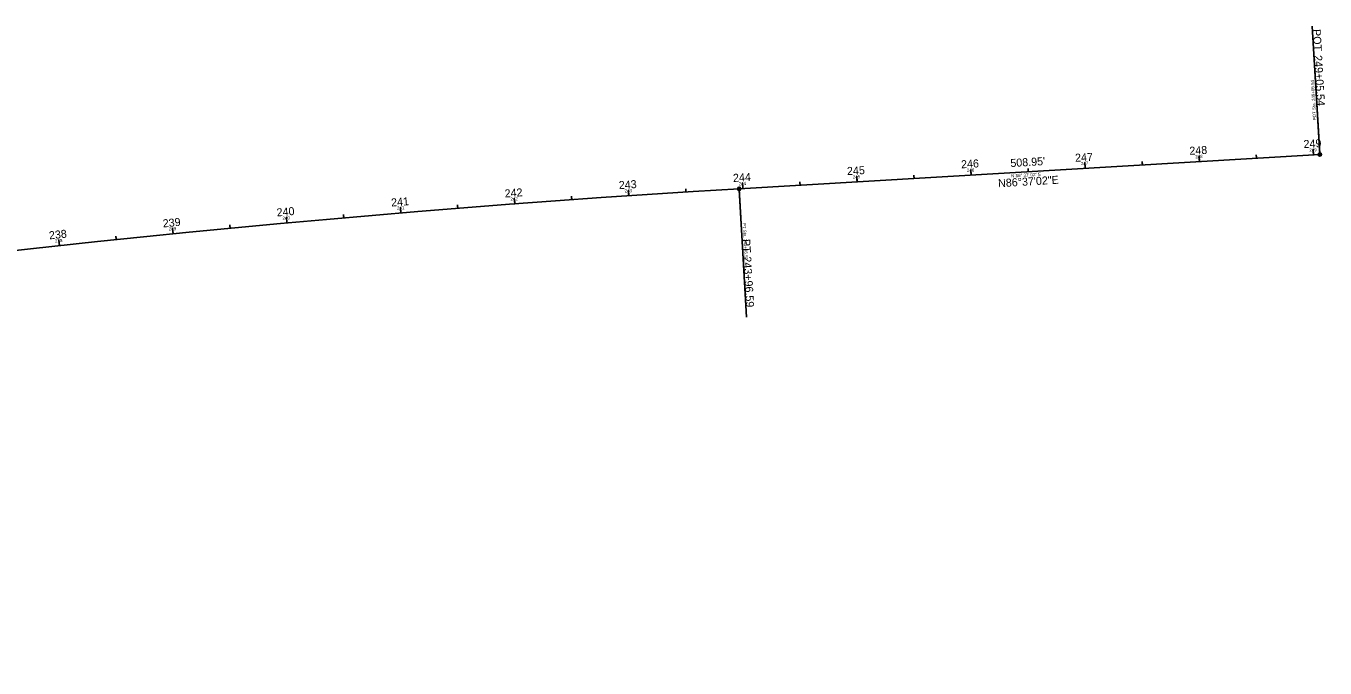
# Model space of a CAD drawing. Extents: x 2129507 to 2138391, y 657622 to 659877.
# Drawn here: x 2137254 to 2138391, y 659316 to 659877 of the extents above; entities that cross this region are included whole.
import ezdxf

# ---------------------------------------------------------------- set-up
doc = ezdxf.new("R2010")
doc.units = 0
for name, color, linetype in [('Default', 7, 'Continuous'), ('GE_X_Alignment_1000_Stations', 7, 'Continuous'), ('GE_X_Alignment_100_Stations', 7, 'Continuous'), ('GE_X_Alignment_500_Stations', 7, 'Continuous'), ('GE_X_CL_20', 7, 'Continuous'), ('MT_P_CL_20', 7, 'Continuous')]:
    doc.layers.add(name, color=color, linetype=linetype)

msp = doc.modelspace()

# ---------------------------------------------------------------- linework, layer by layer
at = {"layer": 'Default'}
for centre in [(2138380.7, 659764.2), (2138386.2, 659764.5), (2138386.2, 659764.5), (2138386.2, 659764.5), (2138181, 659752.4), (2138280.9, 659758.3), (2137981.4, 659740.6), (2137981.4, 659740.6), (2138081.2, 659746.5), (2138132.2, 659749.5), (2138132.2, 659749.5), (2138132.2, 659749.5), (2138132.2, 659749.5), (2138132.2, 659749.5), (2138132.2, 659749.5), (2137878.2, 659734.5), (2137878.2, 659734.5), (2137878.2, 659734.5), (2137881.6, 659734.7), (2137682, 659721.3), (2137781.8, 659728.4), (2137582.3, 659713.4), (2137383.2, 659695.2), (2137482.7, 659704.7), (2137482.7, 659704.7), (2137482.7, 659704.7), (2137283.7, 659684.8)]:
    msp.add_circle(centre, 0.0000833, dxfattribs=at)
at = {"layer": 'GE_X_Alignment_1000_Stations'}
for p, q in [((2138386.2, 659764.5), (2138379.6, 659876.8)), ((2137981.4, 659740.6), (2137981.2, 659743.6)), ((2137878.2, 659734.5), (2137884.8, 659622.2)), ((2137482.7, 659704.7), (2137482.3, 659709.7))]:
    msp.add_line(p, q, dxfattribs=at)
for centre in [(2138386.2, 659764.5), (2137878.2, 659734.5)]:
    msp.add_circle(centre, 1.5, dxfattribs=at)
at = {"layer": 'GE_X_Alignment_100_Stations'}
for p, q in [((2138386.2, 659764.5), (2138379.6, 659876.8)), ((2138280.9, 659758.3), (2138280.6, 659763.3)), ((2138330.8, 659761.2), (2138330.6, 659764.2)), ((2138380.7, 659764.2), (2138380.4, 659769.2)), ((2138081.2, 659746.5), (2138080.9, 659751.5)), ((2138131.1, 659749.4), (2138131, 659752.4)), ((2138181, 659752.4), (2138180.7, 659757.4)), ((2138231, 659755.3), (2138230.8, 659758.3)), ((2137931.5, 659737.6), (2137931.3, 659740.6)), ((2137981.4, 659740.6), (2137981.1, 659745.6)), ((2138031.3, 659743.5), (2138031.1, 659746.5)), ((2137781.8, 659728.4), (2137781.4, 659733.4)), ((2137831.7, 659731.7), (2137831.5, 659734.6)), ((2137878.2, 659734.5), (2137884.8, 659622.2)), ((2137881.6, 659734.7), (2137881.3, 659739.7)), ((2137582.3, 659713.4), (2137581.9, 659718.4)), ((2137632.2, 659717.5), (2137631.9, 659720.5)), ((2137682, 659721.3), (2137681.6, 659726.3)), ((2137731.9, 659725), (2137731.7, 659728)), ((2137482.7, 659704.7), (2137482.3, 659709.7)), ((2137532.5, 659709.2), (2137532.2, 659712.1)), ((2137383.2, 659695.2), (2137382.7, 659700.1)), ((2137432.9, 659700), (2137432.6, 659703)), ((2137283.7, 659684.8), (2137283.2, 659689.8)), ((2137333.4, 659690.1), (2137333.1, 659693.1))]:
    msp.add_line(p, q, dxfattribs=at)
for centre in [(2138386.2, 659764.5), (2137878.2, 659734.5)]:
    msp.add_circle(centre, 1.5, dxfattribs=at)
at = {"layer": 'GE_X_Alignment_500_Stations'}
for p, q in [((2138386.2, 659764.5), (2138379.6, 659876.8)), ((2138380.7, 659764.2), (2138380.5, 659767.2)), ((2138181, 659752.4), (2138180.9, 659755.4)), ((2138280.9, 659758.3), (2138280.7, 659761.3)), ((2137981.4, 659740.6), (2137981.1, 659745.6)), ((2138081.2, 659746.5), (2138081, 659749.5)), ((2137781.8, 659728.4), (2137781.6, 659731.4)), ((2137878.2, 659734.5), (2137884.8, 659622.2)), ((2137881.6, 659734.7), (2137881.4, 659737.7)), ((2137682, 659721.3), (2137681.8, 659724.3)), ((2137482.7, 659704.7), (2137482.3, 659709.7)), ((2137582.3, 659713.4), (2137582.1, 659716.4)), ((2137383.2, 659695.2), (2137382.9, 659698.2)), ((2137283.7, 659684.8), (2137283.4, 659687.8))]:
    msp.add_line(p, q, dxfattribs=at)
for centre in [(2138386.2, 659764.5), (2137878.2, 659734.5)]:
    msp.add_circle(centre, 1.5, dxfattribs=at)
at = {"layer": 'GE_X_CL_20'}
for p, q in [((2138386.2, 659765.5), (2138381.9, 659838.4)), ((2137878.2, 659734.5), (2138386.2, 659764.5)), ((2138330.8, 659761.2), (2138330.7, 659763.2)), ((2138380.7, 659764.2), (2138380.6, 659766.2)), ((2138131.1, 659749.4), (2138131, 659751.4)), ((2138181, 659752.4), (2138180.9, 659754.4)), ((2138231, 659755.3), (2138230.8, 659757.3)), ((2138280.9, 659758.3), (2138280.7, 659760.3)), ((2137981.4, 659740.6), (2137981.3, 659742.6)), ((2138031.3, 659743.5), (2138031.2, 659745.5)), ((2138081.2, 659746.5), (2138081.1, 659748.5)), ((2137781.8, 659728.4), (2137781.6, 659730.4)), ((2137831.7, 659731.7), (2137831.5, 659733.6)), ((2137878.2, 659733.5), (2137882.3, 659663.8)), ((2137881.6, 659734.7), (2137881.4, 659736.7)), ((2137931.5, 659737.6), (2137931.4, 659739.6)), ((2137632.2, 659717.5), (2137632, 659719.5)), ((2137682, 659721.3), (2137681.9, 659723.3)), ((2137731.9, 659725), (2137731.7, 659727)), ((2137482.7, 659704.7), (2137482.5, 659706.7)), ((2137532.5, 659709.2), (2137532.3, 659711.2)), ((2137582.3, 659713.4), (2137582.2, 659715.4)), ((2137383.2, 659695.2), (2137383, 659697.2)), ((2137432.9, 659700), (2137432.7, 659702)), ((2137283.7, 659684.8), (2137283.5, 659686.8)), ((2137333.4, 659690.1), (2137333.2, 659692.1))]:
    msp.add_line(p, q, dxfattribs=at)
for centre in [(2138386.2, 659764.5), (2137878.2, 659734.5)]:
    msp.add_circle(centre, 1, dxfattribs=at)
msp.add_arc((2138602.6, 647478.2), 12277.7, 93.38277, 105.38861, dxfattribs=at)
at = {"layer": 'MT_P_CL_20'}
msp.add_line((2137878.2, 659734.5), (2138386.2, 659764.5), dxfattribs=at)
msp.add_arc((2138602.6, 647478.2), 12277.7, 93.38277, 105.38861, dxfattribs=at)

# ---------------------------------------------------------------- texts
at = {"layer": 'GE_X_Alignment_1000_Stations'}
for s, rotation, p in [('POT', 273.3828, (2138379.9, 659873.9)), ('249+05.54', 273.3828, (2138381.2, 659851.1)), ("508.95'", 3.3828, (2138115.7, 659753.5)), ('N86°37\'02"E', 3.3828, (2138105, 659735.9)), ('240', 5.2335, (2137474, 659710.3)), ('PT', 273.3828, (2137880.9, 659690.4)), ('243+96.59', 273.3828, (2137881.8, 659675.2))]:
    msp.add_text(s, height=7, rotation=rotation, dxfattribs=at).set_placement(p)
at = {"layer": 'GE_X_Alignment_100_Stations'}
for s, rotation, p in [('POT', 273.3828, (2138379.9, 659873.9)), ('249+05.54', 273.3828, (2138381.2, 659851.1)), ('249', 3.3828, (2138372.2, 659770.1)), ('247', 3.3828, (2138172.3, 659758.1)), ('248', 3.3828, (2138272.3, 659764.2)), ('245', 3.3828, (2137972.8, 659746.5)), ('246', 3.3828, (2138072.6, 659752.4)), ("508.95'", 3.3828, (2138115.7, 659753.5)), ('243', 3.8335, (2137773.2, 659734.2)), ('244', 3.3828, (2137873.1, 659740.5)), ('N86°37\'02"E', 3.3828, (2138105, 659735.9)), ('242', 4.3002, (2137673.4, 659726.9)), ('240', 5.2335, (2137474, 659710.3)), ('241', 4.7669, (2137574.1, 659719)), ('239', 5.7002, (2137374.4, 659700.7)), ('238', 6.1669, (2137274.9, 659690.3)), ('PT', 273.3828, (2137880.9, 659690.4)), ('243+96.59', 273.3828, (2137881.8, 659675.2))]:
    msp.add_text(s, height=7, rotation=rotation, dxfattribs=at).set_placement(p)
at = {"layer": 'GE_X_Alignment_500_Stations'}
for s, rotation, p in [('POT', 273.3828, (2138379.9, 659873.9)), ('249+05.54', 273.3828, (2138381.2, 659851.1)), ('245', 3.3828, (2137972.8, 659746.5)), ("508.95'", 3.3828, (2138115.7, 659753.5)), ('N86°37\'02"E', 3.3828, (2138105, 659735.9)), ('240', 5.2335, (2137474, 659710.3)), ('PT', 273.3828, (2137880.9, 659690.4)), ('243+96.59', 273.3828, (2137881.8, 659675.2))]:
    msp.add_text(s, height=7, rotation=rotation, dxfattribs=at).set_placement(p)
at = {"layer": 'GE_X_CL_20'}
for s, rotation, p in [('POT Sta. 249+05.54', 93.3828, (2138383.1, 659794.4)), ('248', 3.3828, (2138277.3, 659761.1)), ('249', 3.3828, (2138377.1, 659767)), ('246', 3.3828, (2138077.6, 659749.3)), ('247', 3.3828, (2138177.3, 659755.2)), ('244', 3.3828, (2137877.9, 659737.5)), ('245', 3.3828, (2137977.7, 659743.4)), ('N 86%%d 37\' 02" E', 3.3828, (2138116.3, 659744.4)), ('243', 3.8335, (2137778.1, 659731.2)), ('241', 4.7669, (2137579.1, 659716.2)), ('242', 4.3002, (2137678.3, 659724.1)), ('240', 5.2335, (2137478.9, 659707.4)), ('239', 5.7002, (2137379.4, 659697.8)), ('PT Sta. 243+96.59', 273.3828, (2137881.3, 659704.6)), ('238', 6.1669, (2137280, 659687.4))]:
    msp.add_text(s, height=2.8, rotation=rotation, dxfattribs=at).set_placement(p)

doc.saveas('drawing.dxf')
